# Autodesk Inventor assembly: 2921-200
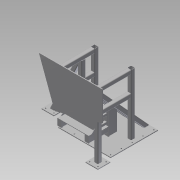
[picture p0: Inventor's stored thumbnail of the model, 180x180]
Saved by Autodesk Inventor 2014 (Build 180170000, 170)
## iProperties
Company: NHTSA/VRTC
Created: 2012-08
Part Number: 2921-200
Document SubType Name: Assembly
Designer: Mike Vanvoorhis
Mass: 129488 g
Surface Area: 61220 cm^2
Volume: 16485.1 cm^3
Density: 7.85482 g/cm^3
Description: IMPACTOR FRAME & STOP ASS'Y.
Project: CHILD SIDE IMPACT SLED
Author: Dave Walker
Title: Impactor Frame & Stop Ass'y.
Subject: Child Side Impact Sled
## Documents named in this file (4)
- B:\VRTC_DWG\BIO\Non-P572\Child Side-Frontal Impact Sled\Side Impact Sled\Impactor_Frame_Assembly_5.iam
- B:\VRTC_DWG\BIO\Non-P572\Child Side-Frontal Impact Sled\Side Impact Sled\Impactor_Frame_Part 7_MIR_MIR.ipt
- B:\VRTC_DWG\BIO\Non-P572\Child Side-Frontal Impact Sled\Side Impact Sled\Impactor_Frame_Assembly_2.iam
- B:\VRTC_DWG\BIO\Non-P572\Child Side-Frontal Impact Sled\Side Impact Sled\Impactor_Frame_Assembly_4.iam
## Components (3 placed, 3 different names)
1. Impactor_Frame_Part 7_MIR_MIR:1 — Flush:1, Mate:1, Flush:2, Mate:2, Flush:3, Mate:3
2. Impactor_Frame_Assembly_2:1 [sub-assembly] — Flush:1, Mate:1, Flush:2
3. Impactor_Frame_Assembly_4:1 [sub-assembly] — Mate:2, Flush:3, Mate:3
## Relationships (6: Flush 3, Mate 3)
- Flush:1: Impactor_Frame_Part 7_MIR_MIR:1 ↔ Impactor_Frame_Assembly_2:1
- Mate:1: Impactor_Frame_Part 7_MIR_MIR:1 ↔ Impactor_Frame_Assembly_2:1
- Flush:2: Impactor_Frame_Part 7_MIR_MIR:1 ↔ Impactor_Frame_Assembly_2:1
- Mate:2: Impactor_Frame_Part 7_MIR_MIR:1 ↔ Impactor_Frame_Assembly_4:1
- Flush:3: Impactor_Frame_Part 7_MIR_MIR:1 ↔ Impactor_Frame_Assembly_4:1
- Mate:3: Impactor_Frame_Part 7_MIR_MIR:1 ↔ Impactor_Frame_Assembly_4:1
